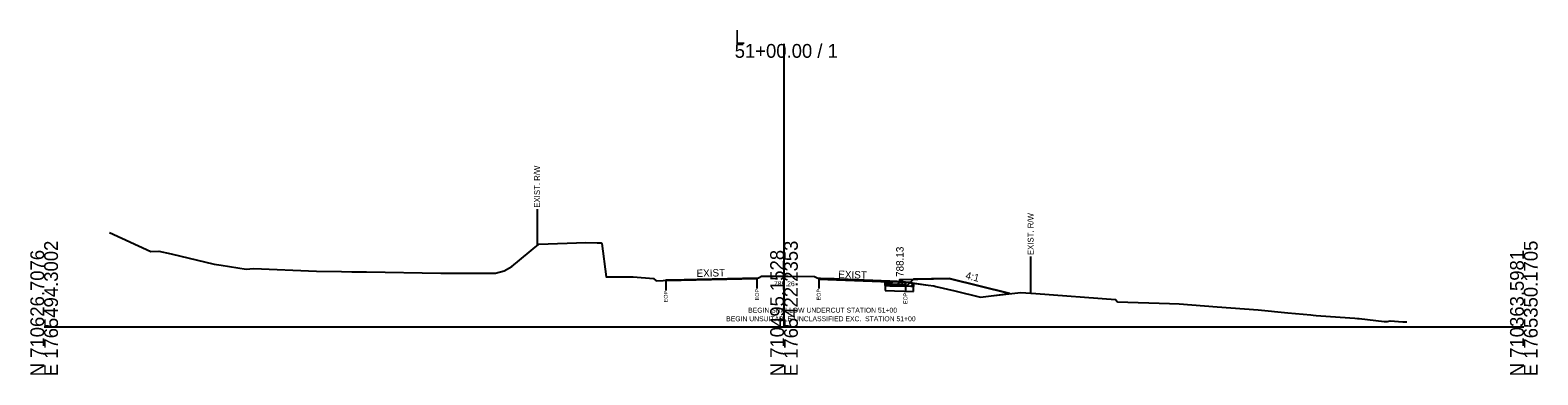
# Model space of a CAD drawing. Extents: x -26 to 5303, y -10 to 9578.
# Drawn here: x 3997.2 to 4302.8, y 990.3 to 1060.1 of the extents above; entities that cross this region are included whole.
import ezdxf

# ---------------------------------------------------------------- set-up
doc = ezdxf.new("R2010")
doc.units = 0
for name, color, linetype in [('Exist Cross Section Cell', 7, 'Continuous'), ('Exist XS Ground Line', 7, 'Continuous'), ('Old_Level_10', 7, 'Continuous'), ('Old_Level_3', 7, 'Continuous'), ('Old_Level_4', 7, 'Continuous'), ('Prop CMT Conc Surface', 7, 'Continuous'), ('Prop CMT Concrete Structures', 7, 'Continuous'), ('Prop CMT Pvmt Course 1', 7, 'Continuous'), ('Prop CMT Pvmt Course 1 CG', 7, 'Continuous'), ('Prop CMT Pvmt Course 2', 7, 'Continuous'), ('Prop CMT Pvmt Course 3', 7, 'Continuous'), ('Prop CMT Pvmt Surface', 7, 'Continuous'), ('Prop CMT Slope Grass', 7, 'Continuous'), ('Prop CMT Subgrade Earthwork', 7, 'Continuous'), ('Prop Shade Light', 7, 'Continuous'), ('Prop XS Earthwork Shape', 7, 'Continuous'), ('Prop XS Hydro Elevations', 7, 'Continuous'), ('Prop XS SE Text', 7, 'Continuous'), ('Prop XS Side Slope Text', 7, 'Continuous'), ('Scratch_Level_5', 7, 'Continuous')]:
    doc.layers.add(name, color=color, linetype=linetype)

msp = doc.modelspace()

# ---------------------------------------------------------------- linework, layer by layer
at = {"layer": 'Exist Cross Section Cell'}
for p, q in [((4150, 1000), (4150, 1057.32)), ((4000, 1000), (4150, 1000)), ((4150, 1000), (4300, 1000))]:
    msp.add_line(p, q, dxfattribs=at)
at = {"layer": 'Exist XS Ground Line'}
msp.add_lwpolyline([(4013.27, 1019.11), (4021.63, 1015.27), (4023.24, 1015.32), (4025.75, 1014.83), (4034.49, 1012.74), (4035.91, 1012.5), (4040.98, 1011.69), (4042.45, 1011.81), (4055.24, 1011.31), (4060.27, 1011.24), (4062.4, 1011.17), (4065.32, 1011.15), (4080.4, 1010.93), (4087.25, 1010.91), (4091.48, 1010.87), (4093.27, 1011.38), (4094.8, 1012.23), (4100.31, 1016.77), (4109.84, 1017.1), (4112.1, 1017.05), (4112.84, 1017.06), (4113.09, 1016.91), (4113.94, 1010.14), (4119.44, 1010.14), (4123.54, 1009.82), (4124.08, 1009.36), (4125.51, 1009.43), (4126.04, 1009.45), (4126.54, 1009.46), (4127.08, 1009.46), (4127.82, 1009.49), (4128.8, 1009.51), (4129.65, 1009.54), (4130.22, 1009.55), (4130.66, 1009.56), (4131.65, 1009.58), (4132.14, 1009.59), (4134.5, 1009.63), (4136.44, 1009.67), (4137.03, 1009.69), (4137.35, 1009.69), (4138.87, 1009.72), (4140.2, 1009.76), (4141.64, 1009.79), (4143.05, 1009.82), (4144, 1009.84), (4144.52, 1009.85), (4144.94, 1010.05), (4145.43, 1010.28), (4150, 1010.26), (4150.78, 1010.26), (4156.16, 1010.23), (4156.61, 1010.03), (4157.04, 1009.84), (4157.39, 1009.81), (4157.98, 1009.78), (4158.41, 1009.76), (4159.13, 1009.75), (4160.15, 1009.72), (4162.46, 1009.63), (4163, 1009.61), (4164.65, 1009.53), (4165.85, 1009.49), (4166.49, 1009.46), (4167.66, 1009.41), (4168.7, 1009.37), (4170.18, 1009.31), (4170.72, 1009.29), (4171.12, 1009.26), (4171.49, 1009.23), (4172.95, 1009.18), (4173.86, 1009.14), (4174.16, 1009.12), (4174.62, 1009.1), (4179.2, 1008.48), (4180.39, 1008.32), (4180.76, 1008.22), (4184.65, 1007.3), (4189.83, 1006.05), (4192.03, 1006.31), (4198.01, 1007.01), (4201.04, 1006.78), (4217.21, 1005.57), (4217.63, 1005.07), (4228.18, 1004.76), (4230.12, 1004.69), (4237.85, 1004.1), (4246.11, 1003.47), (4252.12, 1002.83), (4256.83, 1002.44), (4257.29, 1002.41), (4257.91, 1002.34), (4264.7, 1001.85), (4265.75, 1001.78), (4266.25, 1001.74), (4266.61, 1001.69), (4271.68, 1001.12), (4272.39, 1001.12), (4272.88, 1001.22), (4275.48, 1001.05), (4275.84, 1001.03), (4276.27, 1001.07)], dxfattribs=at)
at = {"layer": 'Old_Level_10'}
for p, q in [((4099.93, 1023.86), (4099.93, 1016.46)), ((4200, 1014.26), (4200, 1006.86)), ((4126.04, 1009.45), (4126.04, 1007.4)), ((4144.52, 1009.85), (4144.52, 1007.8)), ((4157.04, 1009.84), (4157.04, 1007.79)), ((4174.62, 1009.1), (4174.62, 1007.05))]:
    msp.add_line(p, q, dxfattribs=at)
at = {"layer": 'Prop CMT Conc Surface'}
for points in [[(4171.49, 1009.27), (4173.49, 1009.13)], [(4173.49, 1009.13), (4173.49, 1009.63), (4173.99, 1009.63)]]:
    msp.add_lwpolyline(points, dxfattribs=at)
at = {"layer": 'Prop CMT Concrete Structures'}
for points in [[(4171.49, 1009.27), (4173.49, 1009.13), (4173.49, 1009.63), (4173.99, 1009.63)], [(4173.99, 1009.63), (4173.99, 1008.61), (4171.49, 1008.69)], [(4171.49, 1008.69), (4171.49, 1009.27)]]:
    msp.add_lwpolyline(points, dxfattribs=at)
at = {"layer": 'Prop CMT Pvmt Course 1'}
for p, q in [((4144.53, 1009.73), (4126.04, 1009.33)), ((4157.03, 1009.71), (4171.48, 1009.15))]:
    msp.add_line(p, q, dxfattribs=at)
at = {"layer": 'Prop CMT Pvmt Course 1 CG'}
for points in [[(4171.49, 1008.69), (4174.49, 1008.6), (4174.83, 1008.25)], [(4171.49, 1008.35), (4171.49, 1008.69)], [(4174.83, 1008.25), (4171.49, 1008.35)]]:
    msp.add_lwpolyline(points, dxfattribs=at)
at = {"layer": 'Prop CMT Pvmt Course 2'}
for points in [[(4170.49, 1008.72), (4170.49, 1009.05)], [(4170.49, 1009.05), (4171.49, 1009.02)], [(4171.49, 1009.02), (4171.49, 1008.69)], [(4171.49, 1008.69), (4170.49, 1008.72)]]:
    msp.add_lwpolyline(points, dxfattribs=at)
at = {"layer": 'Prop CMT Pvmt Course 3'}
for points in [[(4170.49, 1008.72), (4171.49, 1008.69)], [(4170.49, 1008.38), (4170.49, 1008.72)], [(4171.49, 1008.35), (4170.49, 1008.38)], [(4171.49, 1008.69), (4171.49, 1008.35)]]:
    msp.add_lwpolyline(points, dxfattribs=at)
at = {"layer": 'Prop CMT Pvmt Surface'}
for p, q in [((4144.52, 1009.85), (4126.04, 1009.45)), ((4157.04, 1009.84), (4171.49, 1009.27)), ((4170.49, 1009.3), (4171.49, 1009.27))]:
    msp.add_line(p, q, dxfattribs=at)
at = {"layer": 'Prop CMT Slope Grass'}
msp.add_lwpolyline([(4173.99, 1009.63), (4183.49, 1009.82), (4195.78, 1006.75)], dxfattribs=at)
at = {"layer": 'Prop CMT Subgrade Earthwork'}
msp.add_line((4170.49, 1008.38), (4170.49, 1009.3), dxfattribs=at)
for points in [[(4171.49, 1008.35), (4174.83, 1008.25), (4176.25, 1009.68)], [(4170.49, 1008.38), (4171.49, 1008.35)]]:
    msp.add_lwpolyline(points, dxfattribs=at)
at = {"layer": 'Prop Shade Light'}
for p, q in [((4170.49, 1008.38), (4170.49, 1007.38)), ((4170.49, 1007.38), (4176.25, 1007.21)), ((4176.25, 1007.21), (4176.25, 1008.21))]:
    msp.add_line(p, q, dxfattribs=at)
for points in [[(4174.83, 1008.25), (4174.45, 1008.26), (4173.07, 1008.31), (4171.7, 1008.35), (4171.49, 1008.35), (4170.49, 1008.38)], [(4176.25, 1008.21), (4175.81, 1008.22), (4174.83, 1008.25)]]:
    msp.add_lwpolyline(points, dxfattribs=at)
at = {"layer": 'Prop XS Earthwork Shape'}
for points in [[(4126.04, 1009.45), (4126.54, 1009.46), (4127.08, 1009.46), (4127.82, 1009.49), (4128.44, 1009.5)], [(4128.44, 1009.5), (4126.04, 1009.45), (4126.54, 1009.46), (4127.08, 1009.46), (4127.82, 1009.49)], [(4130.66, 1009.56), (4131.65, 1009.58), (4132.39, 1009.59), (4128.44, 1009.5), (4128.8, 1009.51), (4129.65, 1009.54), (4130.22, 1009.55)], [(4128.44, 1009.5), (4128.8, 1009.51), (4129.65, 1009.54), (4130.22, 1009.55), (4130.66, 1009.56), (4131.65, 1009.58), (4132.39, 1009.59)], [(4132.39, 1009.59), (4133.34, 1009.61), (4134.5, 1009.63), (4136.44, 1009.67), (4137.35, 1009.69), (4138.87, 1009.72), (4140.2, 1009.76), (4141.57, 1009.79)], [(4138.87, 1009.72), (4140.2, 1009.76), (4141.57, 1009.79), (4132.39, 1009.59), (4133.34, 1009.61), (4134.5, 1009.63), (4136.44, 1009.67), (4137.35, 1009.69)], [(4141.57, 1009.79), (4141.64, 1009.79), (4141.78, 1009.79)], [(4141.64, 1009.79), (4141.78, 1009.79), (4141.57, 1009.79)], [(4144.52, 1009.85), (4141.78, 1009.79), (4143.05, 1009.82), (4144, 1009.84)], [(4144, 1009.84), (4144.52, 1009.85), (4141.78, 1009.79), (4143.05, 1009.82)], [(4157.04, 1009.84), (4159.6, 1009.74), (4159.13, 1009.75), (4158.41, 1009.76), (4157.98, 1009.78), (4157.39, 1009.81)], [(4159.13, 1009.75), (4159.6, 1009.74), (4157.04, 1009.84), (4157.39, 1009.81), (4157.98, 1009.78), (4158.41, 1009.76)], [(4159.6, 1009.74), (4164.58, 1009.54), (4163.66, 1009.58), (4163, 1009.61), (4162.46, 1009.63), (4160.15, 1009.72)], [(4167.66, 1009.41), (4168.7, 1009.37), (4170.18, 1009.31), (4170.49, 1009.3), (4171.49, 1009.27), (4164.58, 1009.54), (4165.85, 1009.49), (4166.49, 1009.46)], [(4170.18, 1009.31), (4170.49, 1009.3), (4171.49, 1009.27), (4164.58, 1009.54), (4165.85, 1009.49), (4166.49, 1009.46), (4167.66, 1009.41), (4168.7, 1009.37)], [(4171.49, 1008.35), (4174.83, 1008.25), (4175.55, 1008.98), (4174.62, 1009.1), (4174.16, 1009.12), (4173.86, 1009.14), (4173.49, 1009.16), (4173.49, 1009.13), (4172.49, 1009.2), (4171.49, 1009.23), (4171.12, 1009.26), (4170.72, 1009.29), (4170.49, 1009.3), (4170.49, 1008.38)], [(4172.49, 1009.2), (4173.49, 1009.13), (4173.49, 1009.16), (4173.86, 1009.14), (4174.16, 1009.12), (4174.62, 1009.1), (4175.55, 1008.98), (4174.83, 1008.25), (4171.49, 1008.35), (4170.49, 1008.38), (4170.49, 1009.3), (4170.72, 1009.29), (4171.12, 1009.26), (4171.49, 1009.23)], [(4173.49, 1009.13), (4173.49, 1009.16), (4172.95, 1009.18), (4172.49, 1009.2)], [(4172.49, 1009.2), (4172.95, 1009.18), (4173.49, 1009.16), (4173.49, 1009.13)], [(4180.76, 1008.22), (4184.65, 1007.3), (4189.83, 1006.05), (4192.03, 1006.31), (4195.78, 1006.75), (4183.49, 1009.82), (4176.25, 1009.68), (4175.55, 1008.98), (4179.2, 1008.48), (4180.39, 1008.32)], [(4192.03, 1006.31), (4195.78, 1006.75), (4183.49, 1009.82), (4176.25, 1009.68), (4175.55, 1008.98), (4179.2, 1008.48), (4180.39, 1008.32), (4180.76, 1008.22), (4184.65, 1007.3), (4189.83, 1006.05)]]:
    msp.add_lwpolyline(points, close=True, dxfattribs=at)
at = {"layer": 'Scratch_Level_5'}
for p, q in [((4170.49, 1008.97), (4170.8, 1009.28)), ((4171.29, 1008.36), (4172.14, 1009.21)), ((4172.66, 1008.32), (4173.5, 1009.16)), ((4174.03, 1008.28), (4174.83, 1009.07)), ((4175.63, 1008.23), (4176.25, 1008.85)), ((4176.25, 1008.88), (4176.25, 1008.21))]:
    msp.add_line(p, q, dxfattribs=at)

# ---------------------------------------------------------------- texts
at = {"layer": 'Exist Cross Section Cell'}
for s, p in [('L', (4140, 1057.32)), ('51+00.00 / 1', (4140, 1054.52))]:
    msp.add_text(s, height=2.8, dxfattribs=at).set_placement(p)
for s, p in [('N 710626.7076', (4000, 990)), ('E 1765494.3002', (4002.8, 990)), ('N 710495.1528', (4150, 990)), ('E 1765422.2353', (4152.8, 990)), ('N 710363.5981', (4300, 990)), ('E 1765350.1705', (4302.8, 990))]:
    msp.add_text(s, height=2.8, rotation=90, dxfattribs=at).set_placement(p)
at = {"layer": 'Old_Level_10'}
for s, height, p in [('EXIST. R/W', 1.181, (4100.52, 1024.16)), ('EXIST. R/W', 1.181, (4200.59, 1014.56)), ('EOP', 0.787, (4126.43, 1005)), ('EOP', 0.787, (4144.92, 1005.4)), ('EOP', 0.787, (4157.43, 1005.39)), ('EOP', 0.787, (4175.01, 1004.65))]:
    msp.add_text(s, height=height, rotation=90, dxfattribs=at).set_placement(p)
at = {"layer": 'Old_Level_3'}
msp.add_text('789.26', height=1, dxfattribs=at).set_placement((4147.95, 1008.26))
at = {"layer": 'Old_Level_4'}
msp.add_text('BEGIN SHALLOW UNDERCUT STATION 51+00', height=1, dxfattribs=at).set_placement((4142.73, 1002.9))
at = {"layer": 'Prop XS Hydro Elevations'}
msp.add_text('788.13', height=1.5, rotation=90, dxfattribs=at).set_placement((4174.24, 1010.13))
at = {"layer": 'Prop XS SE Text'}
for rotation, p in [(1.5504, (4132.28, 1010.12)), (358.2816, (4160.99, 1009.93))]:
    msp.add_text('EXIST', height=1.5, rotation=rotation, dxfattribs=at).set_placement(p)
at = {"layer": 'Prop XS Side Slope Text'}
msp.add_text('4:1', height=1.5, rotation=345.9638, dxfattribs=at).set_placement((4186.68, 1009.8))
at = {"layer": 'Scratch_Level_5'}
msp.add_text('BEGIN UNSUITABLE UNCLASSIFIED EXC.  STATION 51+00', height=1, dxfattribs=at).set_placement((4138.28, 1001.16))

doc.saveas('drawing.dxf')
